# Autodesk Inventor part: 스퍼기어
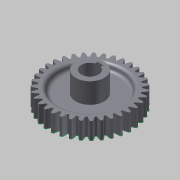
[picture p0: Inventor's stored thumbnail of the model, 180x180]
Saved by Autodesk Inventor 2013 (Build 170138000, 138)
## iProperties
Created: 2013-08
Part Number: 스퍼기어
Material: 강
Document SubType Name: Modeling
Designer: 한국산업디자인학원
Categories: <?xml version="1.0" encoding="UTF-16"?> <MemberInstance><Categories><FamilyTemplate><FamilyTemplateParameter ValueType="xs:double" Id="1" ObjectReferenceKey="da
Density: 1 g/cm^3
CustomPartVersion: 1
Author: 한국산업디자인학원
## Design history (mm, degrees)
sketch "Sketch1"
  geometry: C1 r 37 at (0, 0)
  constraints: 1 centre point
  dimensions: "d0" = 74 diameter of C1 (= da_da)
extrude "Extrusion1" new body sketch "Sketch1" distance "d1" = 15 (= da_b); taper "d2" = 0 deg
workplane "Work Plane2"
feature "피치 지름" dims "d4" = 10, "d5" = 0
workplane "Work Plane8"
workplane "Work Plane9"
feature "스퍼 기어" dims "da_b" = 15, "da_d" = 70, "da_aw" = 70, "da_da" = 74, "da_df" = 65, "da_dw" = 70, angle "da_beta" = 0 deg, "da_lefttooth" = 0, "da_righttooth" = 0
sketch "스케치3"
  geometry: C1 r 12.5 at (0, 0); A1 r 32.5 centre (0, 0) between (9.347, 31.127) and (7.941, 31.515) reference
  constraints: 1 centre point, 1 coincident
  dimensions: "d49" = 25 diameter of C1
extrude "돌출2" join sketch "스케치3" distance "d50" = 3; taper "d52" = 0 deg; dims "d51" = 28, "d53" = 0
sketch "스케치4"
  geometry: L1 (-2.5, 7.071)-(-2.5, 9.371); L2 (-2.5, 9.371)-(2.5, 9.371); L3 (2.5, 9.371)-(2.5, 7.071); C1 r 12.5 at (0, 0) reference; A1 r 7.5 centre (0, 0) between (-2.5, 7.071) and (2.5, 7.071)
  constraints: 6 end point, 2 point on circle, 1 centre point, 1 coincident, 1 parallel, 1 perpendicular, 1 vertical
  dimensions: "d54" = 15 diameter of A1; "d55" = 5 distance between parallel lines of L3 L1; "d56" = 2.5 distance from line of L3 C1.centre; "d57" = 2.3 distance of L2.end L3.end
extrude "돌출3" cut sketch "스케치4" distance "d58" = 36; taper "d59" = 0 deg
sketch "스케치5"
  geometry: C1 r 12.5 at (0, 0) reference; C2 r 27.5 at (0, 0); A1 r 32.5 centre (0, 0) between (9.347, 31.127) and (7.941, 31.515) reference
  constraints: 1 centre point, 1 coincident
  dimensions: "d60" = 55 diameter of C2
extrude "돌출4" cut sketch "스케치5" distance "d61" = 5; taper "d62" = 0 deg
sketch "스케치6"
  geometry: C1 r 12.5 at (0, 0) reference; C2 r 27.5 at (0, 0); A1 r 37 centre (0, 0) between (-5.788, 36.544) and (-7.422, 36.248) reference
  constraints: 1 centre point, 1 coincident
  dimensions: "d63" = 55 diameter of C2
extrude "돌출5" cut sketch "스케치6" distance "d64" = 5; taper "d65" = 0 deg
sketch "스케치7"
  geometry: C1 r 27.5 at (0, 0) reference; A1 r 21.269 centre (-13.327, 31.577) between (7.941, 31.515) and (7.422, 36.248) reference; A2 r 37 centre (0, 0) between (7.422, 36.248) and (5.788, 36.544) reference; A3 r 21.269 centre (23.573, 24.88) between (5.788, 36.544) and (3.639, 32.296) reference; A4 r 32.5 centre (0, 0) between (3.639, 32.296) and (2.186, 32.426) reference; A5 r 21.269 centre (-18.751, 28.689) between (2.186, 32.426) and (0.83, 36.991) reference; A6 r 37 centre (0, 0) between (0.83, 36.991) and (-0.83, 36.991) reference; A7 r 21.269 centre (18.751, 28.689) between (-0.83, 36.991) and (-2.186, 32.426) reference; A8 r 32.5 centre (0, 0) between (-2.186, 32.426) and (-3.639, 32.296) reference; A9 r 21.269 centre (-23.573, 24.88) between (-3.639, 32.296) and (-5.788, 36.544) reference; A10 r 37 centre (0, 0) between (-5.788, 36.544) and (-7.422, 36.248) reference; A11 r 21.269 centre (13.327, 31.577) between (-7.422, 36.248) and (-7.941, 31.515) reference; A12 r 32.5 centre (0, 0) between (-7.941, 31.515) and (-9.347, 31.127) reference; A13 r 21.269 centre (-27.637, 20.271) between (-9.347, 31.127) and (-12.22, 34.924) reference; A14 r 37 centre (0, 0) between (-12.22, 34.924) and (-13.775, 34.34) reference; A15 r 21.269 centre (7.475, 33.449) between (-13.775, 34.34) and (-13.441, 29.591) reference; A16 r 32.5 centre (0, 0) between (-13.441, 29.591) and (-14.755, 28.958) reference; A17 r 21.269 centre (-30.812, 15.011) between (-14.755, 28.958) and (-18.26, 32.18) reference; A18 r 37 centre (0, 0) between (-18.26, 32.18) and (-19.685, 31.329) reference; A19 r 21.269 centre (1.382, 34.246) between (-19.685, 31.329) and (-18.508, 26.715) reference; A20 r 32.5 centre (0, 0) between (-18.508, 26.715) and (-19.688, 25.858) reference; A21 r 21.269 centre (-32.997, 9.268) between (-19.688, 25.858) and (-23.712, 28.403) reference; A22 r 37 centre (0, 0) between (-23.712, 28.403) and (-24.963, 27.31) reference; A23 r 21.269 centre (-4.755, 33.943) between (-24.963, 27.31) and (-22.981, 22.981) reference; A24 r 32.5 centre (0, 0) between (-22.981, 22.981) and (-23.989, 21.927) reference; A25 r 21.269 centre (-34.122, 3.227) between (-23.989, 21.927) and (-28.403, 23.712) reference; A26 r 37 centre (0, 0) between (-28.403, 23.712) and (-29.438, 22.414) reference; A27 r 21.269 centre (-10.739, 32.548) between (-29.438, 22.414) and (-26.715, 18.508) reference; A28 r 32.5 centre (0, 0) between (-26.715, 18.508) and (-27.519, 17.291) reference; A29 r 21.269 centre (-34.15, -2.917) between (-27.519, 17.291) and (-32.18, 18.26) reference; A30 r 37 centre (0, 0) between (-32.18, 18.26) and (-32.967, 16.798) reference; A31 r 21.269 centre (-16.378, 30.108) between (-32.967, 16.798) and (-29.591, 13.441) reference; A32 r 32.5 centre (0, 0) between (-29.591, 13.441) and (-30.164, 12.1) reference; A33 r 21.269 centre (-33.08, -8.968) between (-30.164, 12.1) and (-34.924, 12.22) reference; A34 r 37 centre (0, 0) between (-34.924, 12.22) and (-35.437, 10.641) reference; A35 r 21.269 centre (-21.491, 26.699) between (-35.437, 10.641) and (-31.515, 7.941) reference; A36 r 32.5 centre (0, 0) between (-31.515, 7.941) and (-31.839, 6.519) reference; A37 r 21.269 centre (-30.947, -14.731) between (-31.839, 6.519) and (-36.544, 5.788) reference; A38 r 37 centre (0, 0) between (-36.544, 5.788) and (-36.767, 4.143) reference; A39 r 21.269 centre (-25.913, 22.433) between (-36.767, 4.143) and (-32.426, 2.186) reference; A40 r 32.5 centre (0, 0) between (-32.426, 2.186) and (-32.492, 0.729) reference; A41 r 21.269 centre (-27.819, -20.02) between (-32.492, 0.729) and (-36.991, -0.83) reference; A42 r 37 centre (0, 0) between (-36.991, -0.83) and (-36.916, -2.489) reference; A43 r 21.269 centre (-29.502, 17.445) between (-36.916, -2.489) and (-32.296, -3.639) reference; A44 r 32.5 centre (0, 0) between (-32.296, -3.639) and (-32.1, -5.084) reference; A45 r 21.269 centre (-23.798, -24.665) between (-32.1, -5.084) and (-36.248, -7.422) reference; A46 r 37 centre (0, 0) between (-36.248, -7.422) and (-35.879, -9.041) reference; A47 r 21.269 centre (-32.143, 11.897) between (-35.879, -9.041) and (-31.127, -9.347) reference; A48 r 32.5 centre (0, 0) between (-31.127, -9.347) and (-30.676, -10.734) reference; A49 r 21.269 centre (-19.011, -28.518) between (-30.676, -10.734) and (-34.34, -13.775) reference; A50 r 37 centre (0, 0) between (-34.34, -13.775) and (-33.688, -15.302) reference; A51 r 21.269 centre (-33.751, 5.967) between (-33.688, -15.302) and (-28.958, -14.755) reference; A52 r 32.5 centre (0, 0) between (-28.958, -14.755) and (-28.267, -16.039) reference; A53 r 21.269 centre (-13.613, -31.454) between (-28.267, -16.039) and (-31.329, -19.685) reference; A54 r 37 centre (0, 0) between (-31.329, -19.685) and (-30.414, -21.071) reference; A55 r 21.269 centre (-34.274, -0.155) between (-30.414, -21.071) and (-25.858, -19.688) reference; A56 r 32.5 centre (0, 0) between (-25.858, -19.688) and (-24.948, -20.828) reference; A57 r 21.269 centre (-7.778, -33.38) between (-24.948, -20.828) and (-27.31, -24.963) reference; A58 r 37 centre (0, 0) between (-27.31, -24.963) and (-26.163, -26.163) reference; A59 r 21.269 centre (-33.695, -6.273) between (-26.163, -26.163) and (-21.927, -23.989) reference; A60 r 32.5 centre (0, 0) between (-21.927, -23.989) and (-20.828, -24.948) reference; A61 r 21.269 centre (-1.693, -34.232) between (-20.828, -24.948) and (-22.414, -29.438) reference; A62 r 37 centre (0, 0) between (-22.414, -29.438) and (-21.071, -30.414) reference; A63 r 21.269 centre (-32.034, -12.188) between (-21.071, -30.414) and (-17.291, -27.519) reference; A64 r 32.5 centre (0, 0) between (-17.291, -27.519) and (-16.039, -28.267) reference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
fillet "모깎기1" dims "d66" = 3
body "Solid1"
sketch "Sketch2"
  geometry: C1 r 37 at (0, 0) reference; C2 r 35 at (0, 0)
  constraints: 1 centre point, 1 coincident
  dimensions: "d3" = 70 diameter of C2 (= da_dw)
body "Srf1"
other parameters: "d17" = 0, "d34" = 0.8976 (computed from da_z), "d39" = 0, "d41" = 0, "d47" = 0, "d48" = 0
